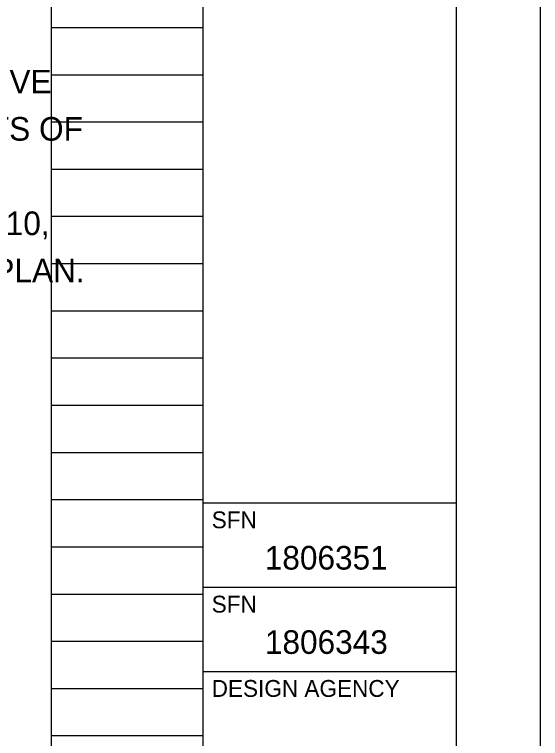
# Model space of a CAD drawing. Extents: x 0 to 34, y 0 to 22.
# Drawn here: x 30.881 to 34, y 4.603 to 8.897 of the extents above; entities that cross this region are included whole.
import ezdxf

# ---------------------------------------------------------------- set-up
doc = ezdxf.new("R2010")
doc.units = 0
for name, color, linetype in [('SH_Border', 7, 'Continuous'), ('SH_Cut_Line', 7, 'Continuous'), ('SH_Data', 7, 'Continuous'), ('SH_Text', 7, 'Continuous')]:
    doc.layers.add(name, color=color, linetype=linetype)

msp = doc.modelspace()

# ---------------------------------------------------------------- linework, layer by layer
at = {"layer": 'SH_Border'}
for p, q in [((32, 0.5), (32, 21.5)), ((32, 6), (33.5, 6)), ((32, 5.5), (33.5, 5.5)), ((32, 5), (33.5, 5))]:
    msp.add_line(p, q, dxfattribs=at)
msp.add_lwpolyline([(1.5, 21.5), (33.5, 21.5), (33.5, 0.5), (1.5, 0.5)], close=True, dxfattribs=at)
at = {"layer": 'SH_Cut_Line'}
msp.add_lwpolyline([(0, 0), (34, 0), (34, 22), (0, 22)], close=True, dxfattribs=at)
at = {"layer": 'SH_Data'}
for p, q in [((31.1, 0.98), (31.1, 21.14)), ((32, 0.98), (32, 21.14)), ((31.1, 8.82), (32, 8.82)), ((31.1, 8.54), (32, 8.54)), ((31.1, 8.26), (32, 8.26)), ((31.1, 7.98), (32, 7.98)), ((31.1, 7.7), (32, 7.7)), ((31.1, 7.42), (32, 7.42)), ((31.1, 7.14), (32, 7.14)), ((31.1, 6.86), (32, 6.86)), ((31.1, 6.58), (32, 6.58)), ((31.1, 6.3), (32, 6.3)), ((31.1, 6.02), (32, 6.02)), ((31.1, 5.74), (32, 5.74)), ((32.75, 5.675), (32.75, 5.675)), ((31.1, 5.46), (32, 5.46)), ((31.1, 5.18), (32, 5.18)), ((32.75, 5.175), (32.75, 5.175)), ((31.1, 4.9), (32, 4.9)), ((31.1, 4.62), (32, 4.62))]:
    msp.add_line(p, q, dxfattribs=at)

# ---------------------------------------------------------------- texts
for s, height, p in [('SFN', 0.1, (32.05, 5.85)), ('1806351', 0.14, (32.3649, 5.605)), ('SFN', 0.1, (32.05, 5.35)), ('1806343', 0.14, (32.3656, 5.105)), ('DESIGN AGENCY', 0.1, (32.05, 4.85))]:
    msp.add_text(s, height=height, dxfattribs=at).set_placement(p)
at = {"layer": 'SH_Text'}
for s, p in [('#6 DOWELS, A801 & A1001 SHALL BE GALVANIZED AND THE ADHESIVE ', (24.66, 8.4287)), ('MATERIAL FOR THE DOWEL HOLE SHALL MEET THE REQUIREMENTS OF ', (24.66, 8.1487)), ('EXISTING BARS SHALL BE INCLUDED FOR PAYMENT UNDER ITEM 510, ', (24.66, 7.5887)), ('DOWEL HOLES WITH NON-SHRINK, NONMETALLIC GROUT AS PER PLAN.', (24.66, 7.3087))]:
    msp.add_text(s, height=0.14, dxfattribs=at).set_placement(p)

doc.saveas('drawing.dxf')
